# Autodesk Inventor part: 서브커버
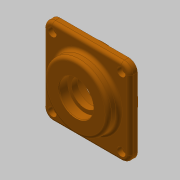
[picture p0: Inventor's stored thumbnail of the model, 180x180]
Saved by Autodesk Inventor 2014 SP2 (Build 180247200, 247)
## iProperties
Created: 2018-09
Part Number: 서브커버
Material: 알루미늄 6061
Document SubType Name: Modeling
Designer: mduedu
Density: 2.71 g/cm^3
Appearance: 주황색
Mass: 206.511 g
Surface Area: 197.007 cm^2
Volume: 76.2032 cm^3
Author: mduedu
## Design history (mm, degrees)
sketch "스케치1"
  geometry: L1 (-40, -40)-(40, -40); L2 (40, -40)-(40, 40); L3 (40, 40)-(-40, 40); L4 (-40, 40)-(-40, -40); L5 (-40, -40)-(40, 40); L6 (40, -40)-(-40, 40); 1 further point
  constraints: 12 end point, 2 midpoint, 2 parallel, 1 horizontal, 1 perpendicular
  dimensions: "d0" = 80 distance of L3.end L2.end; "d1" = 80 distance of L2.end L1.end
extrude "돌출1" new body sketch "스케치1" distance "d2" = 7; taper "d3" = 0 deg
sketch "스케치2"
  geometry: C1 r 30 at (0, 0); 1 further point
  constraints: 1 centre point, 1 coincident
  dimensions: "d4" = 60 diameter of C1
extrude "돌출2" join sketch "스케치2" distance "d5" = 10; taper "d6" = 0 deg
sketch "스케치3"
  geometry: C1 r 32.5 at (0, 0); 1 further point
  constraints: 1 centre point, 1 coincident
  dimensions: "d7" = 65 diameter of C1
extrude "돌출3" join sketch "스케치3" distance "d8" = 9; taper "d9" = 0 deg
sketch "스케치4"
  geometry: L1 (-32.5, -9)-(32.5, -9) reference; L2 (30, 17)-(-30, 17) reference; L3 (0, 17)-(0, -9); L4 (0, -9)-(20, -9); L5 (20, -9)-(20, 3); L6 (20, 3)-(0, 3); L7 (0, 3)-(0, -9); L8 (0, 3)-(12.5, 3); L9 (12.5, 3)-(12.5, 8.7); L10 (12.5, 8.7)-(0, 8.7); L11 (0, 8.7)-(0, 3); L12 (0, 8.7)-(16, 8.7); L13 (16, 8.7)-(16, 17); L14 (16, 17)-(0, 17); L15 (0, 17)-(0, 8.7); 1 further point
  constraints: 26 end point, 6 parallel, 3 horizontal, 3 perpendicular, 2 midpoint, 1 point on line
  dimensions: "d10" = 12 distance of L4.end L5.end; "d12" = 8.3 distance of L12.end L13.end; "d13" = 32 diameter of L13 L3; "d14" = 25 diameter of L9 L3; "d15" = 40 diameter of L5 L3
revolve "회전1" sketch "스케치4" stored, may be unused: angle "d16" = 90 deg
fillet "모깎기1" dims "d17" = 8
fillet "모깎기2" dims "d18" = 3
fillet "모깎기3" dims "d19" = 3
chamfer "모따기1" distance "d20" = 0.8; stored, may be unused: second distance "d21" = 2, angle "d22" = 30 deg
chamfer "모따기2" distance "d23" = 1; stored, may be unused: second distance "d24" = 2, angle "d25" = 30 deg
fillet "모깎기4" dims "d26" = 0.3
sketch "스케치5"
  geometry: A1 r 8 centre (-32, 32) between (-32, 40) and (-40, 32) reference; A2 r 8 centre (-32, -32) between (-40, -32) and (-32, -40) reference; A3 r 8 centre (32, -32) between (32, -40) and (40, -32) reference; A4 r 8 centre (32, 32) between (40, 32) and (32, 40) reference; 5 further points
  constraints: 4 coincident
hole "구멍1" sketch "스케치5" at (-32, 32), (32, 32), (32, -32), (-32, -32) diameter "d27" = 4.5; stored, may be unused: countersink angle "d31" = 90 deg, drill point angle "d33" = 118 deg; dims "d28" = 6, "d29" = 8, "d30" = 4.4, "d32" = 8
node "솔리드1"
